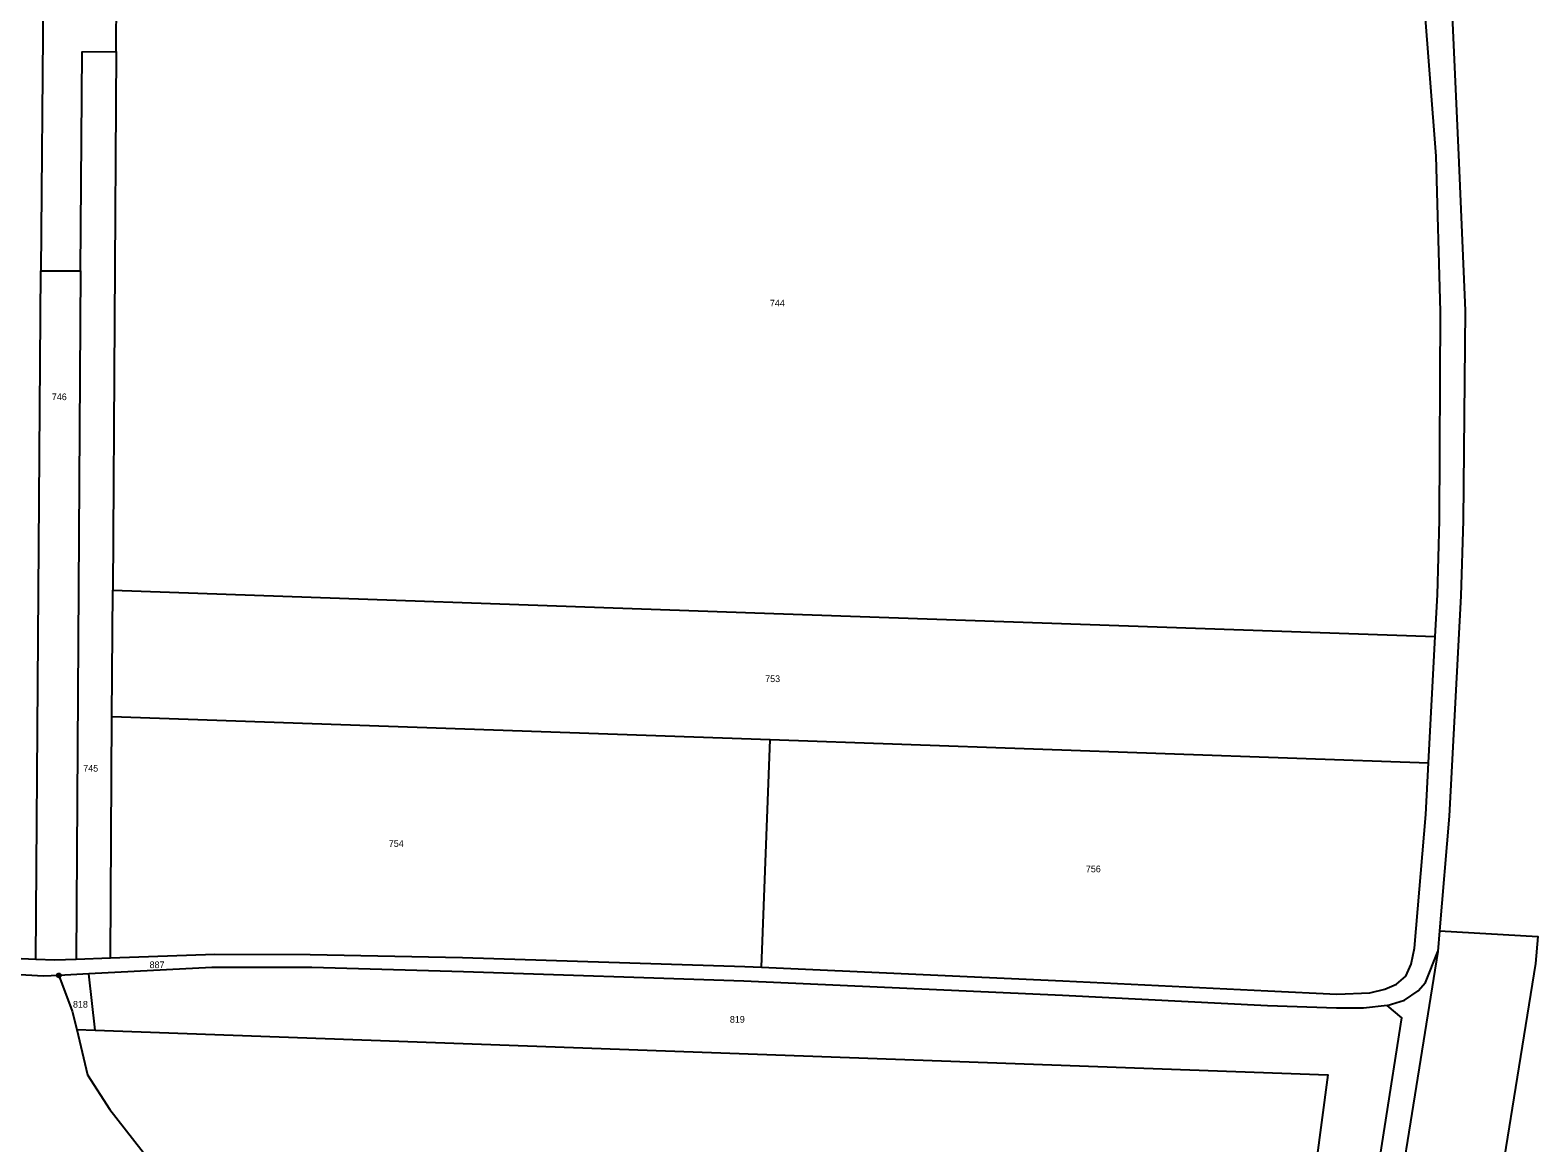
# Model space of a CAD drawing. Extents: x -754445 to -751443, y -1030748 to -1028224.
# Drawn here: x -752451.7 to -752068.2, y -1030202.9 to -1029920 of the extents above; entities that cross this region are included whole.
import ezdxf
from ezdxf.enums import TextEntityAlignment as Align

# ---------------------------------------------------------------- set-up
doc = ezdxf.new("R2010")
doc.units = 0
doc.header["$LTSCALE"] = 0.68
doc.layers.add('1', color=7, linetype='Continuous', lineweight=25)
doc.layers.add('8', color=7, linetype='Continuous', lineweight=25)
doc.layers.add('2', color=7, linetype='Continuous')

msp = doc.modelspace()

# ---------------------------------------------------------------- linework, layer by layer
at = {"layer": '1'}
for p, q in [((-752447.71, -1029819.58), (-752448.91, -1029981.2)), ((-752429.8, -1029925.43), (-752430.65, -1030062.37)), ((-752450.21, -1030156.16), (-752448.91, -1029981.2)), ((-752448.91, -1029981.2), (-752438.82, -1029981.2)), ((-752096.04, -1030106.24), (-752094.35, -1030074.17))]:
    msp.add_line(p, q, dxfattribs=at)
for points in [[(-752210.85, -1029598.51), (-752202.9, -1029613.43), (-752196.1, -1029626.91), (-752164.5, -1029677.22), (-752141.8, -1029712.13), (-752130.09, -1029731.01), (-752122.07, -1029746.38), (-752110.76, -1029772.03), (-752103.34, -1029794.29), (-752097.44, -1029818.68), (-752093.44, -1029845.4), (-752091.89, -1029870.03), (-752090.2, -1029912.61), (-752088.45, -1029951.67), (-752086.73, -1029991.22), (-752087.26, -1030044.65), (-752087.79, -1030063.79), (-752090.75, -1030119.86), (-752093.21, -1030149.03)], [(-752438.82, -1029981.2), (-752438.46, -1029925.53), (-752429.8, -1029925.43), (-752429.71, -1029911.1)], [(-752094.35, -1030074.17), (-752093.79, -1030063.55), (-752093.26, -1030044.54), (-752093.02, -1029991.51), (-752094.06, -1029952.03), (-752097.13, -1029912.5)], [(-752438.82, -1029981.2), (-752439.95, -1030156.16), (-752431.23, -1030155.85), (-752430.85, -1030094.49), (-752430.65, -1030062.37)], [(-752430.65, -1030062.37), (-752262.5, -1030068.27), (-752094.35, -1030074.17)], [(-752430.85, -1030094.49), (-752263.5, -1030100.36), (-752096.04, -1030106.24)], [(-752431.23, -1030155.85), (-752404.72, -1030154.89), (-752380.48, -1030155), (-752341.75, -1030155.76), (-752269.95, -1030158.08), (-752265.68, -1030158.27), (-752263.5, -1030100.36)], [(-752265.68, -1030158.27), (-752189.05, -1030161.7), (-752136.87, -1030164.29), (-752119.33, -1030165.08), (-752110.96, -1030164.73), (-752107.13, -1030163.83), (-752104.16, -1030162.53), (-752101.78, -1030160.53), (-752100.43, -1030157.45), (-752099.6, -1030153.42), (-752096.74, -1030119.45), (-752096.04, -1030106.24)], [(-752093.21, -1030149.03), (-752093.65, -1030154.27), (-752109.89, -1030255.12)], [(-752093.21, -1030149.03), (-752068.24, -1030150.46), (-752068.82, -1030157.31), (-752081.43, -1030235.61)], [(-752478.36, -1030154.36), (-752461.37, -1030155.68), (-752450.21, -1030156.16)], [(-752450.21, -1030156.16), (-752445.4, -1030156.36), (-752439.95, -1030156.16)], [(-752106.53, -1030168.01), (-752102.15, -1030166.61), (-752098.69, -1030164.22), (-752096.8, -1030162.13), (-752093.65, -1030154.27)], [(-752444.34, -1030160.32), (-752448.3, -1030160.52), (-752461.79, -1030159.74), (-752485.11, -1030158.54), (-752517.65, -1030157.86), (-752526.32, -1030158.62), (-752535.32, -1030161.63), (-752542.54, -1030165.3)], [(-752439.83, -1030174.11), (-752435.14, -1030174.28), (-752436.72, -1030159.92), (-752444.34, -1030160.32)], [(-752444.34, -1030160.32), (-752440.97, -1030169.41), (-752439.83, -1030174.11)], [(-752106.53, -1030168.01), (-752112.57, -1030168.67), (-752119.43, -1030168.67), (-752137.01, -1030168.06), (-752189.15, -1030165.45), (-752270.14, -1030161.77), (-752341.42, -1030159.44), (-752380, -1030158.31), (-752405.42, -1030158.31), (-752436.72, -1030159.92)], [(-752163.64, -1030410.21), (-752127.02, -1030299.43), (-752120.67, -1030275.98), (-752115.78, -1030254.01), (-752102.81, -1030171.14), (-752106.53, -1030168.01)], [(-752439.83, -1030174.11), (-752437.05, -1030185.62), (-752431.38, -1030194.39), (-752421.38, -1030207.19), (-752419.3, -1030212.39), (-752418.63, -1030220.29), (-752422.02, -1030230.52), (-752425.01, -1030237.63), (-752429.44, -1030245.19), (-752435.75, -1030259.17), (-752439.96, -1030269.02), (-752447.22, -1030281.16)], [(-752435.14, -1030174.28), (-752278.41, -1030179.94), (-752121.68, -1030185.6), (-752133.55, -1030274.9), (-752142.73, -1030316.17), (-752163.64, -1030410.21)]]:
    msp.add_lwpolyline(points, dxfattribs=at)
at = {"layer": '8'}
for radius in [0.5, 0.0303]:
    msp.add_circle((-752444.34, -1030160.3199), radius, dxfattribs=at)

# ---------------------------------------------------------------- texts
at = {"layer": '2'}
for s, p in [('744', (-752261.639, -1029990.236)), ('746', (-752444.249, -1030014.056)), ('753', (-752262.839, -1030085.746)), ('745', (-752436.259, -1030108.516)), ('754', (-752358.559, -1030127.646)), ('756', (-752181.289, -1030134.096)), ('887', (-752419.389, -1030158.476)), ('818', (-752438.879, -1030168.516)), ('819', (-752271.819, -1030172.356))]:
    msp.add_text(s, height=1.7, dxfattribs=at).set_placement(p, align=Align.CENTER)

doc.saveas('drawing.dxf')
